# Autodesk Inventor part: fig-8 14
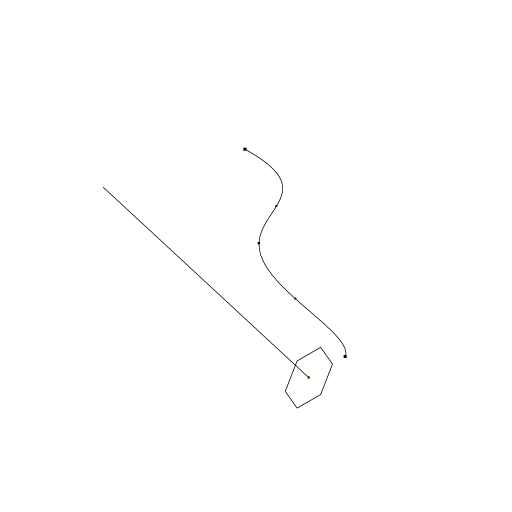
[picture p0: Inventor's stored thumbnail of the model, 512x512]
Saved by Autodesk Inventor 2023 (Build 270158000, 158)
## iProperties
Created: 2004-05
Part Number: fig-8 14
Document SubType Name: Modeling
Designer: CADCIM Technologies
Manufacturer: Standard
Standards Organization: Custom
Density: 1 g/cm^3
Material: Generic
Appearance: Default
Author: CADCIM Technologies
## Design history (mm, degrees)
workplane "Work Plane2"
sketch "Sketch7"
  geometry: L1 (-42.583, 6.068)-(-42.583, 0.37) reference; 5 further points
  constraints: 1 point on line, 5 other
sketch "Sketch8"
  geometry: L1 (-42.583, 3.219)-(-107.269, 18.236); L2 (-42.583, 6.068)-(-42.583, 0.37) reference
  constraints: 2 end point, 1 midpoint
sketch "Sketch2"
  geometry: L1 (-5.697, 0)-(-2.849, 4.934); L2 (-2.849, 4.934)-(2.849, 4.934); L3 (2.849, 4.934)-(5.697, 0); L4 (5.697, 0)-(2.849, -4.934); L5 (2.849, -4.934)-(-2.849, -4.934); L6 (-2.849, -4.934)-(-5.697, 0); 2 further points
  constraints: 12 end point, 1 coincident, 12 other
